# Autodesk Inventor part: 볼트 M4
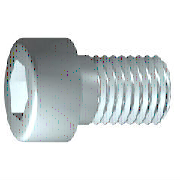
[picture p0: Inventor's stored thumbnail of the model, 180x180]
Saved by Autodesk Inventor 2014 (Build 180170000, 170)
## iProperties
IsCustomPart: 0
Created: 2009-02
Part Number: 볼트 M4
Material: 강철, 연강
Description: 6각머리 태핑 나사
Document SubType Name: Modeling
Standard: KS B 1003
Standards Organization: KS
Language: ko-KR
Size Designation: M 4 x 12
Categories: <MemberInstance><Categories><Category DisplayName="조임쇠" InternalName="e4da775c-781d-43d5-af7c-5136215cf5a6" Mnemonic="FSTN"><Category DisplayName="볼트" InternalN
Density: 1 g/cm^3
Appearance: 차가운 흰색
Author: pww
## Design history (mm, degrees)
sketch "스케치1"
  geometry: L1 (-1, 0)-(12, 0); L2 (12, 0)-(12, 2); L3 (12, 2)-(1.75, 2); L4 (1.75, 2)-(1.32, 2); L5 (1.32, 2)-(0, 2); L6 (0, 2)-(0, 3.5); L7 (0, 3.5)-(-4, 3.5); L8 (-4, 3.5)-(-4, 1.732); L9 (-4, 1.732)-(-2, 1.732); L10 (-2, 1.732)-(-1, 0); L11 (-7.2, 0)-(15.2, 0) reference; L12 (0, -0.7)-(0, 4.2) reference; L13 (1.75, 2)-(0, 2)
  constraints: 22 end point, 6 parallel, 2 collinear, 2 perpendicular, 1 horizontal, 1 point on line
  dimensions: "d1" = 10.25 distance from line of L3.end L2 (= GEL); "d2" = 0.42952 distance of L4.end L3.end (computed from GAL); "d3" = 4 distance between parallel lines of L8 L6 (= KOH); "d4" = 2 distance of L8.end L9.end (= INTI); "d5" = 60 deg angle of L10 L1; "d6" = 4 diameter of L3 L1 (= GD); "d7" = 4 diameter of L5 L1 (= BDM); "d8" = 3.4641 diameter of L9 L1 (= 1.1547 x SW); "d9" = 7 diameter of L7 L1 (= KOD); "d26" = 12 distance between parallel lines of L12 L2 (= NLG)
revolve "본체" sketch "스케치1" stored, may be unused: angle "d10" = 90 deg
sketch "스케치2"
  geometry: L1 (0, -4.9)-(0, 4.9) reference; L2 (-4.9, 0)-(4.9, 0) reference; L3 (1.732, 0)-(0.866, -1.5); L4 (0.866, -1.5)-(-0.866, -1.5); L5 (-0.866, -1.5)-(-1.732, 0); L6 (-1.732, 0)-(-0.866, 1.5); L7 (-0.866, 1.5)-(0.866, 1.5); L8 (0.866, 1.5)-(1.732, 0); 2 further points
  constraints: 12 end point, 1 coincident, 1 horizontal alignment, 1 point on line, 12 other
extrude "슬롯" join sketch "스케치2" stored distance "d11" = 10; taper "d12" = 0 deg
workplane "Work Plane1"
fillet "Fillet2" dims "d30" = 0.1 (= R)
body "Solid1"
fillet "모깎기1" dims "d17" = 0.4 (= RR)
feature "스레드" dims "d13" = 10.25 (= GEL), "d14" = 0
chamfer "모따기1" distance "d15" = 0.42941 (= -0.5 x SPD + 0.5 x GD); stored, may be unused: second distance "d16" = 0.42941 (= GUL), angle "d27" = 45 deg
other parameters: "GD" = 4 (= NND) [user parameter; used in 2 equation terms], "NLG" = 12 [user parameter; used in 1 equation term], "GEL" = 10.25 [user parameter; used in 2 equation terms], "KOD" = 7 [user parameter; used in 1 equation term], "KOH" = 4 [user parameter; used in 1 equation term], "INTI" = 2 [user parameter; used in 1 equation term], "GAL" = 0.42941 (= 0.61345 x PTC) [user parameter; used in 1 equation term], "GUL" = 0.42941 (= 0.61345 x PTC) [user parameter; used in 1 equation term], "BDM" = 4 (= NND) [user parameter; used in 1 equation term], "SW" = 3 [user parameter; used in 2 equation terms], "RR" = 0.4 [user parameter; used in 1 equation term], "SPD" = 3.14117 (= NND - 1.2269 x PTC) [user parameter; used in 1 equation term], "d19" = 0, "d28" = 0, "d29" = 0, "R" = 0.1 [user parameter; used in 1 equation term], "PHH" = 0.2 [user parameter], "GD1" = 3.14117 (= THREADDIA - 1.2269 x PTC) [user parameter], "THREADDIA" = 4 [user parameter; used in 1 equation term], "FAWI" = 45 deg [user parameter], "TPU" = 14.28571 (computed from PTC) [user parameter], "PTC" = 0.7 [user parameter; used in 5 equation terms], "NND" = 4 [user parameter; used in 3 equation terms], "TOA" = 30 deg [user parameter], "E0" = 3.465 (= 1.155 x SW) [user parameter]
